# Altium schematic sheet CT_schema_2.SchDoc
size 187 x 169 mm
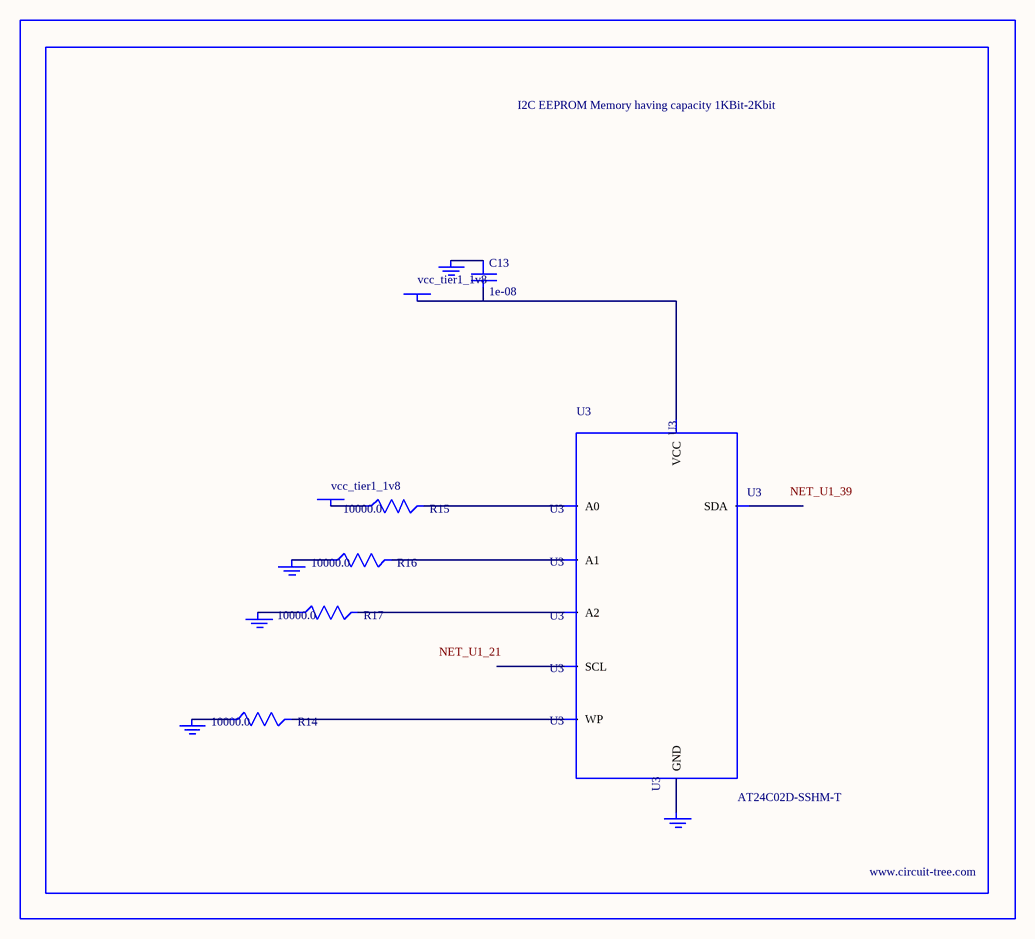
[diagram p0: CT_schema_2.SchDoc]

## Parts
BORDER1  (no value)
C13  1e-08  [C0402]
GND_INSTANCE_1_0  (no value)
GND_INSTANCE_1_1  (no value)
GND_INSTANCE_1_2  (no value)
GND_INSTANCE_1_3  (no value)
GND_INSTANCE_1_4  (no value)
POWER_INSTANCE_1_0  vcc_tier1_1v8
POWER_INSTANCE_1_1  vcc_tier1_1v8
R14  10000.0  [R0603]
R15  10000.0  [R0603]
R16  10000.0  [R0603]
R17  10000.0  [R0603]
U3  AT24C02D-SSHM-T  [AT24C02D]

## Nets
NetC13_1: C13.1 GND_INSTANCE_1_3.0(GND)
NetC13_2: C13.2 POWER_INSTANCE_1_1.0(PWR) U3.8(VCC)
NetGND_INSTANCE_1_0_0: GND_INSTANCE_1_0.0(GND) R16.1
NetGND_INSTANCE_1_1_0: GND_INSTANCE_1_1.0(GND) R17.1
NetGND_INSTANCE_1_2_0: GND_INSTANCE_1_2.0(GND) R14.1
NetGND_INSTANCE_1_4_0: GND_INSTANCE_1_4.0(GND) U3.4(GND)
NetPOWER_INSTANCE_1_0_0: POWER_INSTANCE_1_0.0(PWR) R15.1
NetR14_2: R14.2 U3.7(WP)
NetR15_2: R15.2 U3.1(A0)
NetR16_2: R16.2 U3.2(A1)
NetR17_2: R17.2 U3.3(A2)

Not connected (* = marked no-connect by the designer): U3 5(SDA) 6(SCL)

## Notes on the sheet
- Labels drawn without touching a wire or pin: NET_U1_21, NET_U1_39

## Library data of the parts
BORDER1 = BORDER_PAGE1
C13 = C0402C103K3RAC
GND_INSTANCE_1_0-GND_INSTANCE_1_4 = GND
POWER_INSTANCE_1_0 POWER_INSTANCE_1_1 = PWR
R14-R17 = RC0603JR-0710KL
